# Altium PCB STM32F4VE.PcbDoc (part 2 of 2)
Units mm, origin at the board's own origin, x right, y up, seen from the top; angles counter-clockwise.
Board outline 98.7 x 95.5 mm, 2 copper layers (Top Layer, Bottom Layer); 103 components, 124 nets, 470 pads, 212 vias.
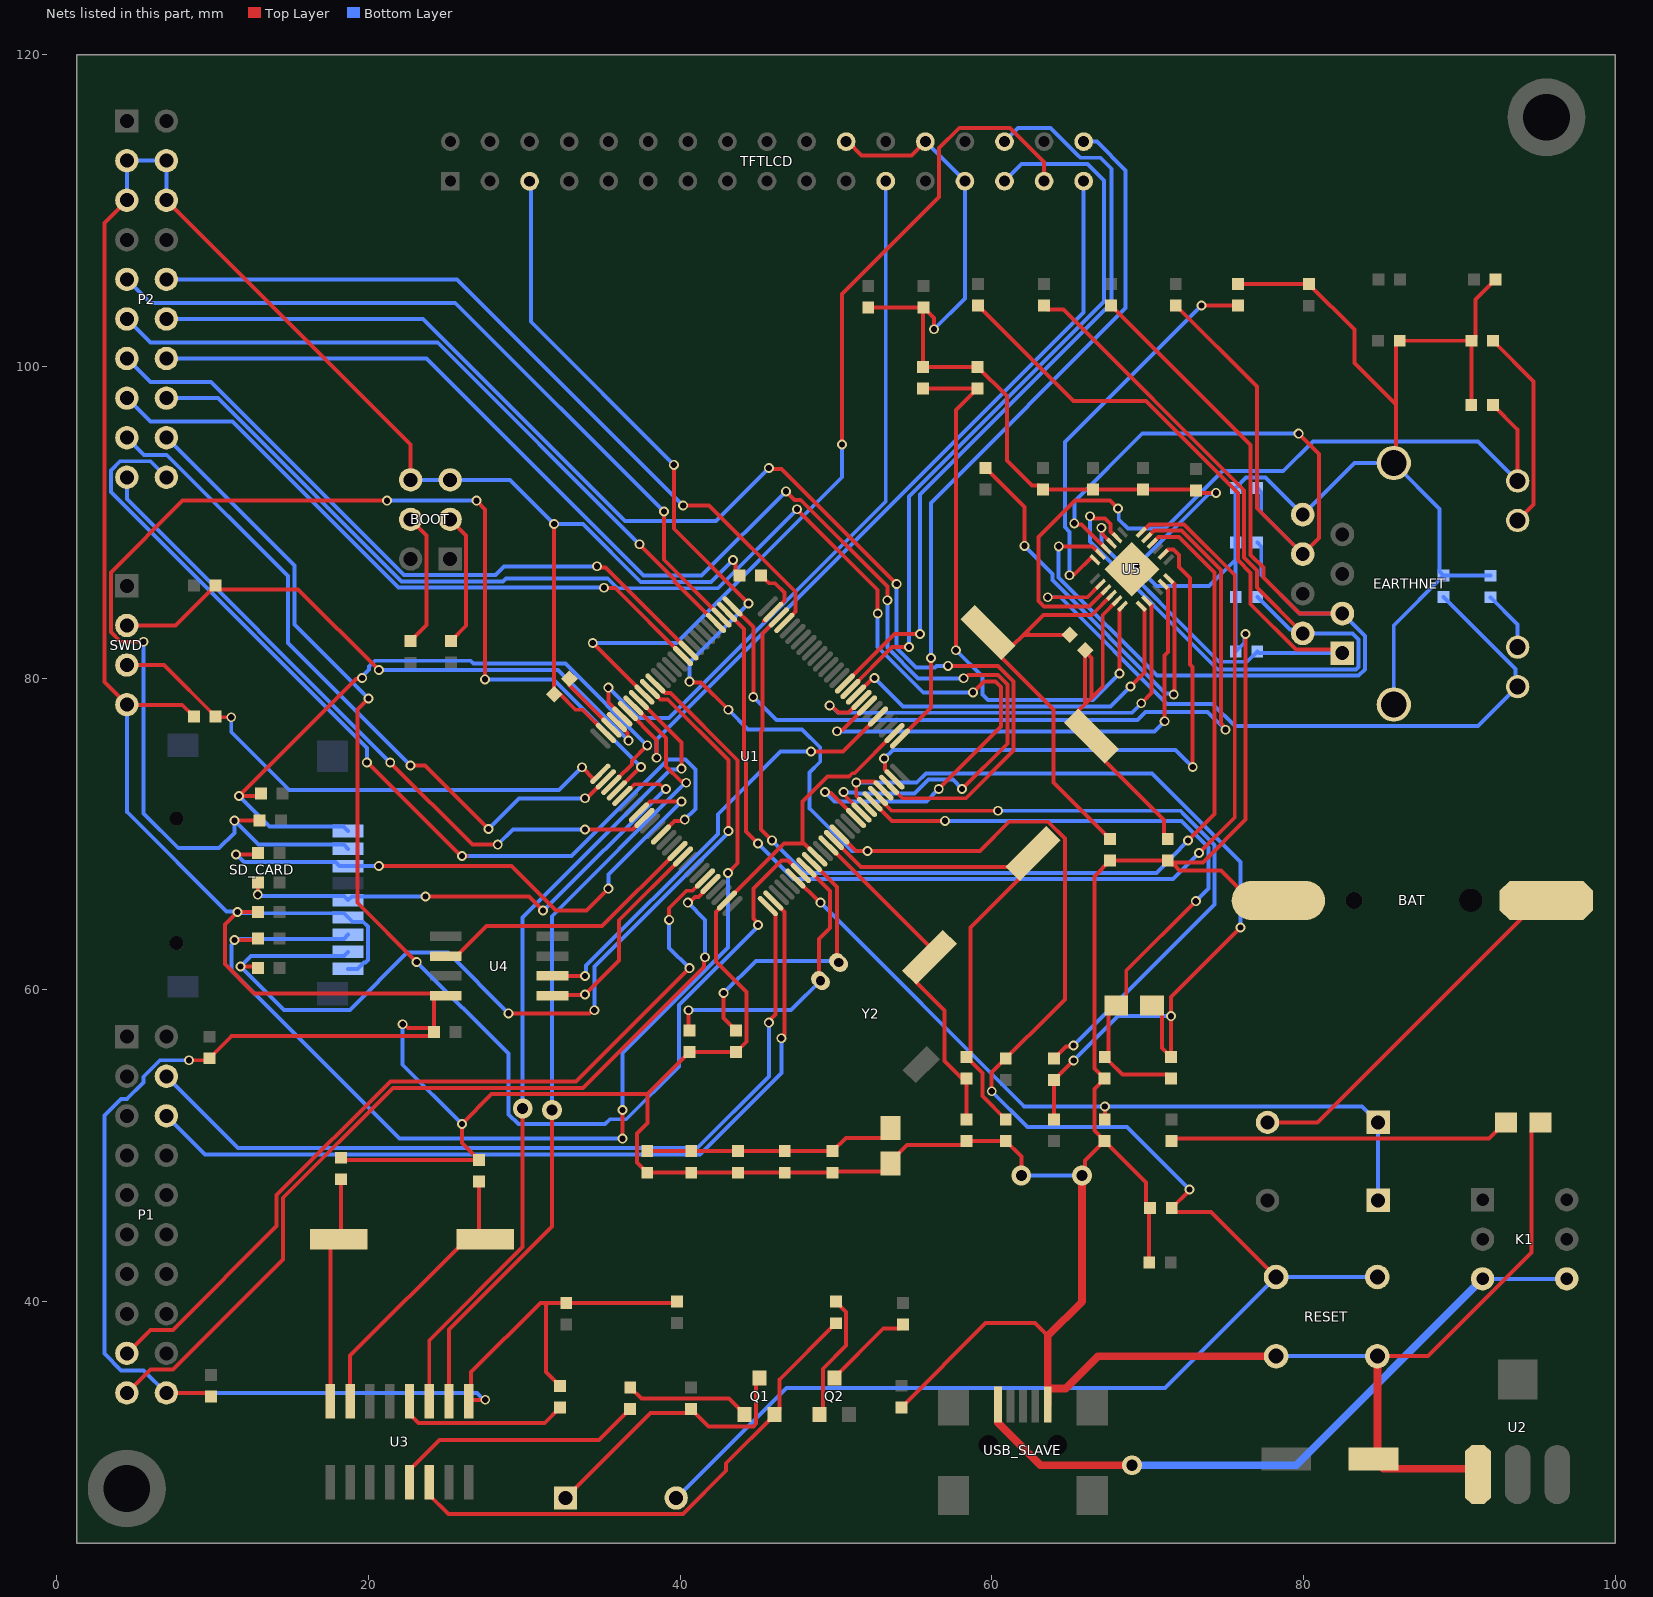
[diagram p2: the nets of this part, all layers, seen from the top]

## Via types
v1: diameter 0.635, hole 0.4, Top Layer to Bottom Layer, 197 vias
v2: diameter 1.27, hole 0.711, Top Layer to Bottom Layer, 15 vias

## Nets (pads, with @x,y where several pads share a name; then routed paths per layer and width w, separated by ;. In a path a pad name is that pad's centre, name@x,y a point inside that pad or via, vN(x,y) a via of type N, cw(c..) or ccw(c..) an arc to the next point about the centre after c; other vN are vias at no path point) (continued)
GND: BAT.2 BOOT.5 BOOT.6 C3.1 C4.1 C5.1 C6.1 C7.1 C8.1 C9.2 C10.2 C11.1 C12.1 C13.1 C14.1 C15.1 C16.1 C19.2 C20.2 C21.1 C22.1 C23.2 C24.1 C25.1 C26.1 C27.2 C28.1 C29.1 C30.1 C31.1 C32.1 C33.1 C34.2 C35.2 C36.1 C37.1 C38.1 C39.1 C40.1 C41.1 C42.1 C43.1 C44.1 C45.2 C46.2 DS1.2 EARTHNET.8 EARTHNET.13 EARTHNET.14 P1.20 P2.3 P2.4 P2.5 P2.6 R2.1 R18.1 R32.1 R33.1 R38.2 R39.2 R41.1 R42.1 RESET.2 SD_CARD.6 SD_CARD.9 SWD.4 TFTLCD.22 TFTLCD.26 TFTLCD.27 U1.10 U1.27 U1.74 U1.99 U2.1 U3.1 U4.4 U5.25 USB_SLAVE.5 | length 652.8
  Top Layer w0.254: P2.5@4.5,110.68 4.5,110.667 3.064,109.231 3.064,79.759 4.5,78.323 SWD.4@4.5,78.31 4.509,78.301 8.054,78.301 R18.1@8.814,77.541 ; P1.20@7.04,34.14 9.674,34.14 C43.1@9.9,33.914 ; P2.6@7.04,110.68 7.04,110.667 22.698,95.009 22.698,92.745 BOOT.6@22.707,92.736 ; v1(8.489,55.489) 9.672,55.489 11.23,57.048 23.948,57.048 C27.2@24.202,57.302 ; C28.1@12.914,65 v1(11.6,65) 10.803,64.203 10.803,61.653 12.673,59.782 24.093,59.782 24.312,59.563 24.202,59.452 C27.2@24.202,57.302 ; C26.1@18.398,49.087 C25.1@26.898,49.087 ; v1(22.2,57.8) 22.303,57.8 22.548,57.556 23.948,57.556 C27.2@24.202,57.302 ; U4.4@24.379,59.63 U4.4@24.956,59.63 ; U3.1@26.445,33.6 26.545,33.7 v1(27.5,33.7) ; U3.1@26.445,33.7 26.597,33.852 26.597,35.475 31.041,39.918 31.549,39.918 ; C25.1@27.1,49.086 26,50.186 v1(26,51.4) 27.914,53.314 37.9,53.314 ; v1(31.924,89.9) C11.1@31.924,78.981 32.283,78.981 33.282,77.982 33.74,77.982 U1.74@35.237,76.485 ; C24.1@32.046,34.84 31.4,35.486 31.4,39.77 31.549,39.918 ; C22.1@39.713,39.918 31.549,39.918 ; C14.1@40.6,56.014 37.9,53.314 ; C14.1@40.6,56.014 C13.1@43.6,56.014 44.262,56.676 44.262,59.858 42.3,61.82 42.3,65.002 43.015,65.716 U1.99@43.015,65.737 46.678,69.4 47.958,69.4 ; v1(43.4,87.6) 43.4,87.497 43.56,87.337 43.56,86.854 C12.1@43.814,86.6 ; U1.10@48.813,68.565 48.793,68.565 47.958,69.4 ; TFTLCD.22@50.662,114.441 50.773,114.441 51.653,113.562 54.85,113.562 55.729,114.441 TFTLCD.26@55.742,114.441 ; C46.2@52.079,103.802 C45.2@55.615,103.802 ; C3.1@53.438,48.922 54.564,50.047 58.128,50.047 C10.2@58.382,50.301 C9.2@60.9,50.301 61.9,49.302 v2(61.9,48.1) ; C3.1@53.502,48.858 52.994,48.35 49.87,48.35 C4.1@49.792,48.272 C8.1@37.893,48.272 37.234,48.931 37.234,50.79 37.9,51.456 37.9,53.314 ; U1.27@53.763,76.485 51.184,73.906 51.052,73.906 50.844,73.698 49.454,73.698 47.857,72.101 47.857,69.501 47.958,69.4 ; C21.1@54.2,33.214 59.6,38.614 62.786,38.614 63.6,37.8 ; v1(56.3,102.4) 56.3,103.117 55.632,103.785 55.598,103.752 C30.1@55.598,99.986 C29.1@59.097,99.986 60.969,98.113 60.969,93.987 62.588,92.368 63.046,92.368 C31.1@63.3,92.114 73.036,92.114 73.25,91.9 v1(74.4,91.9) ; USB_SLAVE.5@63.6,34.3 USB_SLAVE.5@63.723,34.423 ; v2(65.8,48.1) 65.994,48.294 65.994,49.058 C15.1@67.251,50.314 ; C19.2@70.109,42.502 70.109,45.939 C16.1@70.169,46 69.915,46.254 69.915,47.649 C15.1@67.251,50.314 ; C35.2@71.298,68.302 C34.2@67.598,68.302 66.592,67.295 66.592,54.973 R2.1@67.251,54.314 66.592,53.655 66.592,50.973 C15.1@67.251,50.314 ; C35.2@71.552,68.186 73.552,68.186 76.292,70.927 v1(76.292,82.848) ; C35.2@71.597,68.048 71.691,68.048 72.06,67.678 74.71,67.678 76.652,65.737 BAT.2@78.402,65.737 ; R32.1@75.811,105.307 80.337,105.307 83.268,102.375 83.268,100.224 85.932,97.561 ; C20.2@84.5,29.9 C20.2@84.751,30.151 ; RESET.2@84.751,36.5 87.996,36.5 94.638,43.142 94.638,50.99 95.146,51.498 DS1.2@95.211,51.498 ; EARTHNET.14@85.802,93.816 85.932,93.945 85.932,97.561 ; C42.1@86.186,101.663 R41.1@90.79,101.663 ; C42.1@86.186,101.663 85.932,101.409 85.932,97.561 ; R38.2@90.778,97.542 90.778,101.65 R41.1@90.79,101.663 ; U2.1@90.837,29.277 U2.1@91.21,28.904 ; C41.1@92.335,105.591 91.044,104.301 91.044,101.917 R41.1@90.79,101.663
  Top Layer w0.5: USB_SLAVE.5@63.6,33.4 63.6,34.3 63.6,37.8 65.8,40 v2(65.8,48.1) ; USB_SLAVE.5@63.723,34.423 64.754,34.423 66.826,36.495 78.246,36.495 RESET.2@78.251,36.5 ; C20.2@84.751,30.151 RESET.2@84.751,36.5 ; C20.2@85.123,29.277 U2.1@90.837,29.277
  Bottom Layer w0.254: SWD.4@4.5,78.31 4.509,78.301 4.509,71.434 10.901,65.042 11.558,65.042 v1(11.6,65) 11.703,65 11.78,64.923 18.427,64.923 18.973,64.377 19.668,64.377 19.979,64.066 19.979,61.934 19.816,61.771 19.721,61.771 19.3,61.35 SD_CARD.9@18.7,61.35 ; P2.5@4.5,110.68 P2.3@4.5,113.22 P2.4@7.04,113.22 P2.6@7.04,110.68 ; v1(8.489,55.489) 6.614,55.489 5.554,54.43 5.554,54.059 4.495,52.999 4.123,52.999 3.064,51.94 3.064,36.66 4.136,35.588 5.579,35.588 7.027,34.14 P1.20@7.04,34.14 7.049,34.131 26.966,34.131 27.397,33.7 v1(27.5,33.7) ; v1(22.2,57.8) 22.2,55.2 v1(26,51.4) ; BOOT.6@22.707,92.736 BOOT.5@25.247,92.736 25.256,92.726 29.098,92.726 v1(31.924,89.9) 33.761,89.9 37.477,86.184 41.984,86.184 v1(43.4,87.6) ; TFTLCD.26@55.742,114.441 TFTLCD.27@58.282,111.901 58.273,111.892 58.273,104.373 v1(56.3,102.4) ; v2(61.9,48.1) v2(65.8,48.1) ; v1(74.4,91.9) 74.327,91.827 73.927,91.827 v1(69.3,87.2) 70.589,85.91 73.946,85.91 75.66,87.625 ; v1(76.292,82.848) 76.219,82.776 76.219,82.281 C39.1@75.66,81.722 75.66,87.625 ; RESET.2@78.251,36.5 RESET.2@84.751,36.5 ; EARTHNET.13@85.802,78.316 85.802,83.4 R39.2@88.998,86.597 88.744,86.851 88.744,90.873 EARTHNET.14@85.802,93.816 83.279,93.816 79.969,90.506 79.951,90.506 77.573,92.884 76.322,92.884 C36.1@75.66,92.222 75.66,87.625 ; R39.2@89.011,86.584 R42.1@92,86.584
I2C_SCL: P1.17 U1.95 | length 55
  Top Layer w0.254: P1.17@4.5,36.68 6.011,38.191 7.466,38.191 14.114,44.838 14.114,46.835 21.407,54.127 33.329,54.127 v1(40.6,61.398) ; v1(39.3,64.5) 39.3,65.244 40.422,66.366 40.795,66.366 41.58,67.151 U1.95@41.601,67.151
  Bottom Layer w0.254: v1(39.3,64.5) 39.3,62.698 v1(40.6,61.398)
I2C_SDA: P1.19 U1.96 | length 57
  Top Layer w0.254: P1.19@4.5,34.14 6.011,35.651 7.466,35.651 14.521,42.705 14.521,46.667 21.575,53.721 33.767,53.721 41.528,61.482 41.528,62.027 v1(41.601,62.1) ; v1(40.5,65.6) 40.603,65.6 40.963,65.96 41.195,65.96 U1.96@41.84,66.604
  Bottom Layer w0.254: v1(40.5,65.6) 41.601,64.499 v1(41.601,62.1)
LCD_BL: TFTLCD.23 U1.71 | length 47.1
  Top Layer w0.254: v1(35.4,79.4) 35.4,78.464 36.298,77.566 U1.71@36.298,77.546
  Bottom Layer w0.254: v1(35.4,79.4) 37.343,77.457 39.301,77.457 53.202,91.357 TFTLCD.23@53.202,111.901
LINK_LED: EARTHNET.12 R38.1 U5.3 | length 50.8
  Top Layer w0.254: U5.3@67.337,85.691 66.249,84.603 63.353,84.603 63.003,84.953 63.003,89.066 65.34,91.403 67.597,91.403 v1(68.1,90.9) ; R38.1@92.162,97.54 93.75,95.952 EARTHNET.12@93.75,92.666
  Bottom Layer w0.254: v1(68.1,90.9) 68.154,90.846 68.154,90.201 68.753,89.603 71.128,89.603 74.816,93.29 78.709,93.29 80.614,95.195 91.221,95.195 EARTHNET.12@93.75,92.666
NetBAT_1: BAT.1 D2.1 | length 23.8
  Top Layer w0.254: D2.1@77.701,51.5 80.9,51.5 94.639,65.239 95.104,65.239 BAT.1@95.602,65.737
NetBOOT_3: BOOT.3 R5.2 | length 8.6
  Top Layer w0.254: BOOT.3@25.247,90.196 26.276,89.166 26.276,83.373 R5.2@25.302,82.399
NetBOOT_4: BOOT.4 R6.1 | length 8.7
  Top Layer w0.254: R6.1@22.707,82.386 23.736,83.415 23.736,89.166 BOOT.4@22.707,90.196
NetC1_1: C1.1 C2.1 R2.2 U1.20 | length 44
  Top Layer w0.254: U1.20@52.349,72.101 53.596,70.854 v1(57,70.854) ; R2.2@67.252,55.698 R2.2@67.372,55.818 ; C1.1@71.5,54.314 71.246,54.568 68.382,54.568 67.492,55.459 67.492,55.818 R2.2@67.372,55.818 ; v1(73.1,65.7) 68.635,61.235 68.635,59.506 68.127,58.998 C2.1@68,58.998 67.492,58.49 67.492,55.938 R2.2@67.372,55.818
  Bottom Layer w0.254: v1(57,70.854) 72.179,70.854 73.901,69.132 73.901,66.501 v1(73.1,65.7)
NetC9_1: C9.1 R4.2 U1.13 Y1.2 | length 31.3
  Top Layer w0.254: U1.13@49.874,69.626 51.608,67.892 61.792,67.892 61.792,67.156 58.637,64.001 58.637,55.952 R4.2@58.383,55.698 59.403,54.679 59.403,53.184 C9.1@60.902,51.686
NetC10_1: C10.1 R4.1 U1.12 Y1.1 | length 21.8
  Top Layer w0.254: U1.12@49.52,69.272 56,62.793 Y1.1@56,62.1 55.147,61.247 55.147,60.51 56.964,58.694 56.964,55.451 R4.1@58.1,54.314 ; C10.1@58.383,51.686 R4.1@58.382,54.314
NetC11_2: C11.2 U1.73 | length 4.2
  Top Layer w0.254: C11.2@32.904,79.958 32.904,79.525 U1.73@35.59,76.838
NetC12_2: C12.2 U1.49 | length 4.3
  Top Layer w0.254: C12.2@45.198,86.598 45.697,86.1 46.1,86.1 46.7,85.5 46.7,84.999 45.985,84.284 U1.49@45.985,84.263 45.964,84.263 U1.49@45.389,83.688
NetC13_2: C13.2 U1.9 Y2.1 | length 18.2
  Top Layer w0.254: v1(42.8,59.8) 42.8,58.2 C13.2@43.6,57.4 ; U1.9@48.46,68.212 50.068,66.603 50.068,61.866 Y2.1@50.174,61.76
  Bottom Layer w0.254: v1(42.8,59.8) 44.866,61.866 50.068,61.866 Y2.1@50.174,61.76
NetC14_2: C14.2 U1.8 Y2.2 | length 18.9
  Top Layer w0.254: v1(40.538,58.7) 40.538,57.462 C14.2@40.602,57.399 ; U1.8@48.106,67.858 49.611,66.353 49.611,63.972 48.908,63.269 48.908,60.706 Y2.2@49.014,60.6
  Bottom Layer w0.254: v1(40.538,58.7) 47.115,58.7 Y2.2@49.093,60.679
NetC24_2: C24.2 U3.4 | length 11.1
  Top Layer w0.254: U3.4@22.635,33.6 22.635,32.8 23.214,32.221 31.317,32.221 C24.2@32.298,33.201
NetC25_2: C25.2 U3.7 Y3.1 | length 18.6
  Top Layer w0.254: U3.7@18.825,33.6 18.825,36.531 26.294,44 Y3.1@27.5,44 27.098,44.402 C25.2@27.098,47.702
NetC26_2: C26.2 U3.8 Y3.2 | length 14.4
  Top Layer w0.254: U3.8@17.555,33.6 17.555,43.479 18.076,44 Y3.2@18.102,44 18.244,44.142 C26.2@18.244,47.703
NetC29_2: C29.2 C30.2 U5.6 | length 38.2
  Top Layer w0.254: C30.2@55.597,98.602 C29.2@59.095,98.602 57.7,97.206 57.7,81.806 v1@57.706,81.8 ; v1(68.2,80.3) 68.206,80.306 U5.6@68.206,84.436
  Bottom Layer w0.254: v1(57.7,81.8) 59.397,80.103 59.397,78.959 59.753,78.603 66.503,78.603 v1(68.2,80.3)
NetC34_1: C34.1 R40.1 U5.4 Y4.1 | length 28.1
  Top Layer w0.254: Y4.1@59.755,82.945 Y4.1@60.544,82.156 ; 62.281,82.945 62.441,82.785 ; R40.1@65.015,82.785 62.441,82.785 ; C34.1@67.6,69.686 63.977,73.309 63.977,77.987 60.608,81.356 60.608,82.092 61.344,82.092 62.037,82.785 ; U5.4@67.691,85.337 66.42,84.067 63.318,84.067 62.037,82.785 ; 62.037,82.785 62.441,82.785
NetC35_1: C35.1 R40.2 U5.5 Y4.2 | length 25.4
  Top Layer w0.254: Y4.2@66.4,76.3 65.547,77.153 65.547,77.89 65.993,78.335 ; Y4.2@66.443,76.343 66.443,75.52 71.046,70.918 71.046,69.94 C35.1@71.3,69.686 ; U5.5@68.045,84.984 67.126,84.066 67.126,79.469 66.4,78.743 ; 65.993,78.335 R40.2@65.993,81.805 65.993,81.714 66.4,81.307 66.4,78.743 ; 65.993,78.335 66.4,78.743
NetD3_2: D3.2 Q1.3 R23.1 | length 18.2
  Top Layer w0.254: D3.2@32.65,27.4 38.11,32.86 40.446,32.86 R23.1@40.7,33.114 41.817,31.998 44.716,31.998 44.879,32.161 44.879,34.881 Q1.3@45.1,35.102
NetDS1_1: DS1.1 R19.1 | length 21.9
  Top Layer w0.254: R19.1@71.545,50.313 71.703,50.471 91.908,50.471 92.936,51.498 DS1.1@93.001,51.498
NetEARTHNET_10: EARTHNET.10 R42.2 | length 3.9
  Bottom Layer w0.254: R42.2@92.002,85.2 93.75,83.451 EARTHNET.10@93.75,82.002
NetEARTHNET_11: EARTHNET.11 R41.2 | length 13
  Top Layer w0.254: R41.2@92.175,101.661 94.779,99.056 94.779,91.159 EARTHNET.11@93.75,90.13
NetQ1_1: Q1.1 R24.1 U3.14 | length 33.9
  Top Layer w0.254: U3.14@23.905,28.4 23.905,27.6 25.134,26.371 40.176,26.371 42.952,29.146 42.952,29.629 46.05,32.727 Q1.1@46.05,32.752 46.373,33.075 46.373,34.987 R24.1@50,38.614
NetQ1_2: Q1.2 R22.2 | length 8.1
  Top Layer w0.254: R22.2@36.802,34.498 37.526,33.775 43.152,33.775 44.15,32.777 Q1.2@44.15,32.752
NetQ2_2: Q2.2 R24.2 | length 8.2
  Top Layer w0.254: Q2.2@48.95,32.752 49.171,32.973 49.171,35.693 50.66,37.183 50.66,39.34 R24.2@50.002,39.999
NetQ2_3: Q2.3 R25.2 | length 5.8
  Top Layer w0.254: Q2.3@49.9,35.102 49.9,35.127 53.04,38.267 54.044,38.267 R25.2@54.298,38.521
NetR1_2: R1.2 U1.21 | length 40.7
  Top Layer w0.254: U1.21@52.973,72.106 53.578,71.5 v1(60.4,71.5) ; R1.2@64.002,55.599 64.769,56.366 65.18,56.366 v1(65.253,56.439)
  Bottom Layer w0.254: v1(60.4,71.5) 72.108,71.5 72.348,71.26 74.308,69.3 74.308,65.494 v1(65.253,56.439)
NetR22_1: R22.1 U3.13 | length 16.6
  Top Layer w0.254: U3.13@22.635,28.4 22.635,29.2 24.552,31.117 34.802,31.117 R22.1@36.8,33.114
NetR31_2: R31.2 U5.12 | length 27.4
  Top Layer w0.254: R31.2@59.602,93.499 62.1,91 v1(62.1,88.5) ; U5.12@71.37,86.398 71.37,86.395 71.72,86.045 71.72,79 v1(71.68,78.96)
  Bottom Layer w0.254: v1(62.1,88.5) 63.894,86.706 63.894,86.302 71.163,79.033 71.607,79.033 v1(71.68,78.96)
NetR32_2: R32.2 U5.24 | length 25.6
  Top Layer w0.254: v1(65,86.615) 65.073,86.688 65.33,86.688 66.436,87.793 66.439,87.793 U5.24@66.63,87.602 ; v1(73.457,103.923) R32.2@75.81,103.923
  Bottom Layer w0.254: v1(65,86.615) 65,89.4 64.703,89.697 64.703,95.169 v1(73.457,103.923)
PA0: P2.12 U1.23 | length 83.3
  Top Layer w0.254: v1(45.7,93.5) 45.756,93.444 46.502,93.444 v1(53.9,86.045) ; U1.23@53.41,73.161 53.43,73.161 54.289,72.303 58.349,72.303 61.41,75.364 61.41,79.784 60.393,80.8 v1(57.2,80.8)
  Bottom Layer w0.254: P2.12@7.04,103.06 23.515,103.06 36.472,90.103 42.303,90.103 v1(45.7,93.5) ; v1(53.9,86.045) 53.9,81.957 55.154,80.703 56.347,80.703 56.444,80.8 57.024,80.8 v1@57.103,80.721
PA15: P2.17 U1.77 | length 45
  Top Layer w0.254: v1(22.7,74.4) 23.633,74.4 v1(27.7,70.333) ; v1(33.9,72.3) 34.001,72.3 35.216,73.515 U1.77@35.237,73.515
  Bottom Layer w0.254: P2.17@4.5,95.44 5.604,94.336 7.06,94.336 14.844,86.552 14.844,82.256 v1(22.7,74.4) ; v1(27.7,70.333) 29.667,72.3 v1(33.9,72.3)
PB10: P2.10 U1.47 | length 51
  Top Layer w0.254: v1(40.2,91.097) 41.857,91.097 47.4,85.554 47.4,84.285 46.692,83.577 U1.47@46.692,83.556
  Bottom Layer w0.254: P2.10@7.04,105.6 25.697,105.6 v1(40.2,91.097)
PB14: P2.9 U1.53 | length 49
  Top Layer w0.254: v1(38.964,90.7) 38.964,87.607 U1.53@42.661,83.91
  Bottom Layer w0.254: P2.9@4.5,105.6 6.011,104.089 25.574,104.089 v1(38.964,90.7)
PB15: P2.11 U1.54 | length 46
  Top Layer w0.254: v1(37.4,88.6) 37.4,88.596 39.648,86.348 39.648,86.216 U1.54@42.308,83.556
  Bottom Layer w0.254: P2.11@4.5,103.06 6.011,101.549 24.451,101.549 v1(37.4,88.6)
PC2: P2.16 U1.17 | length 87.1
  Top Layer w0.254: v1(47.5,90.846) 52.686,85.66 v1(52.686,84.152) ; v1(49.3,72.7) 49.373,72.627 49.701,72.627 U1.17@51.288,71.04 ; v1(56.6,72.9) 60.597,76.897 60.597,79.447 60.247,79.797 59.497,79.797 v1(58.8,79.1)
  Bottom Layer w0.254: P2.16@7.04,97.98 10.352,97.98 22.112,86.22 28.641,86.22 28.832,86.41 35.361,86.41 35.993,85.778 42.432,85.778 v1(47.5,90.846) ; v1(49.3,72.7) 49.897,72.103 55.803,72.103 v1(56.6,72.9) ; v1(52.686,84.152) 52.686,82.022 55.608,79.1 v1(58.8,79.1)
PC3: P2.14 U1.18 | length 87.5
  Top Layer w0.254: v1(46.8,92) 47.358,91.442 47.747,91.442 53.303,85.887 v1(53.303,85.009) ; v1(50.5,72.7) 50.573,72.627 50.573,72.463 U1.18@51.642,71.394 ; v1(58.102,72.9) 61.003,75.802 61.003,79.615 60.415,80.203 58.506,80.203 58.303,80 v1(58.2,80)
  Bottom Layer w0.254: P2.14@7.04,100.52 23.716,100.52 37.646,86.591 41.391,86.591 v1(46.8,92) ; v1(50.5,72.7) 50.543,72.657 51.199,72.657 51.253,72.603 55.059,72.603 55.953,73.497 57.505,73.497 v1(58.102,72.9) ; v1(53.303,85.009) 53.303,81.98 55.283,80 v1(58.2,80)
PC13: P2.18 U1.7 | length 83.6
  Top Layer w0.254: v1(20,78.7) 19.303,78.003 19.303,65.597 v1(23.1,61.8) ; v1(45,64.172) 45,64.275 44.703,64.572 44.703,66.501 46.503,68.302 46.935,68.302 47.732,67.505 U1.7@47.753,67.505
  Bottom Layer w0.254: P2.18@7.04,95.44 15.25,87.23 15.25,83.45 v1(20,78.7) ; v1(23.1,61.8) 28.986,55.914 28.986,52.021 29.621,51.386 35.196,51.386 35.514,51.703 36.547,51.703 39.941,55.097 39.941,59.022 45,64.08 v1(45,64.172)
PD3: P2.19 U1.84 | length 44.4
  Top Layer w0.254: v1(21.4,74.6) 26.677,69.323 28.177,69.323 v1@28.2,69.3 ; v1(33.9,70.3) 36.951,70.3 37.691,71.04 U1.84@37.712,71.04
  Bottom Layer w0.254: P2.19@4.5,92.9 4.5,91.5 v1(21.4,74.6) ; v1(28.3,69.323) 29.277,70.3 v1(33.9,70.3)
PD6: P2.20 U1.87 | length 61.9
  Top Layer w0.254: v1(19.9,74.596) 19.952,74.596 25.948,68.6 v1@26.3,68.6 ; U1.87@38.772,69.98 39.647,70.854 40.227,70.854 v1(40.3,70.927)
  Bottom Layer w0.254: P2.20@7.04,92.9 6.011,93.929 4.074,93.929 3.471,93.326 3.471,91.955 19.9,75.525 v1(19.9,74.596) ; v1(26,68.6) 33.044,68.6 39.241,74.797 40.342,74.797 40.997,74.142 40.997,71.624 v1(40.3,70.927)
PD12: P2.13 U1.59 | length 44.3
  Top Layer w0.254: v1(34.672,87.188) 34.744,87.115 35.214,87.115 U1.59@40.54,81.788
  Bottom Layer w0.254: P2.13@4.5,100.52 6.011,99.009 9.897,99.009 22.281,86.626 28.144,86.626 28.705,87.188 v1(34.672,87.188)
PD13: P2.15 U1.60 | length 42.5
  Top Layer w0.254: v1(35.113,85.813) 35.117,85.809 35.812,85.809 U1.60@40.187,81.435
  Bottom Layer w0.254: P2.15@4.5,97.98 6.011,96.469 11.288,96.469 21.944,85.813 v1(35.113,85.813)
PWDN: P1.4 U1.1 | length 53.8
  Top Layer w0.254: U1.1@45.631,65.383 46.116,64.899 46.116,58.419 45.7,58.003 v1(45.7,57.9)
  Bottom Layer w0.254: P1.4@7.04,54.46 11.64,49.86 41.104,49.86 45.7,54.456 v1(45.7,57.9)
RESET: C16.2 D3.1 R16.2 RESET.1 TFTLCD.5 U1.14 | length 169.4
  Top Layer w0.254: v1(39.603,93.7) 39.603,89.597 v1(44.4,84.8) ; v1(40.6,79.784) 40.66,79.724 41.358,79.724 v1(43.1,77.982) ; U1.14@50.228,69.98 51.288,68.919 59.238,68.919 61.113,70.794 63.614,70.794 64.694,69.714 64.694,59.391 60,54.697 v1(60,53.5) ; v1(72.7,47.2) 72.7,47.145 C16.2@71.554,45.998 71.808,45.744 74.086,45.744 RESET.1@78.251,41.58
  Bottom Layer w0.254: TFTLCD.5@30.344,111.895 30.423,111.816 30.423,102.88 v1(39.603,93.7) ; D3.1@39.75,27.4 39.763,27.4 46.826,34.463 71.133,34.463 RESET.1@78.251,41.58 RESET.1@84.751,41.58 ; v1(40.6,79.784) 40.6,81 v1(44.4,84.8) ; v1(43.1,77.982) 44.354,76.728 47.816,76.728 48.997,75.547 48.997,74.645 48.297,73.945 48.297,71.659 51.037,68.919 v1(52.034,68.919) ; v1(60,53.5) 62.285,51.214 68.686,51.214 v1(72.7,47.2)
RMII_CRS_DV: U1.32 U5.11 | length 32.9
  Top Layer w0.254: v1(50.071,76.6) 50.144,76.673 50.416,76.673 U1.32@51.995,78.253 ; U5.11@71.016,86.045 71.016,86.042 71.313,85.745 71.313,81.696 71.083,81.466 71.083,77.258 v1(71.1,77.241)
  Bottom Layer w0.254: v1(50.071,76.6) 70.459,76.6 v1(71.1,77.241)
RMII_REF_CLK: U1.24 U5.14 | length 37.3
  Top Layer w0.254: v1(53.1,74.847) 53.15,74.797 53.15,74.148 53.763,73.536 U1.24@53.763,73.515 ; U5.14@71.016,87.955 71.019,87.955 71.316,88.252 71.68,88.252 72.02,87.912 72.02,87.14 72.735,86.425 72.735,80.883 72.9,80.718 v1(72.9,74.3)
  Bottom Layer w0.254: v1(53.1,74.847) 53.652,75.399 71.801,75.399 v1(72.9,74.3)
RMII_RXD0: U1.33 U5.8 | length 30
  Top Layer w0.254: v1(49.6,78.253) 49.703,78.253 50.156,77.8 50.815,77.8 51.621,78.606 U1.33@51.642,78.606 ; v1(69.6,78.4) 70.253,79.053 70.253,84.684 69.955,84.981 U5.8@69.955,84.984
  Bottom Layer w0.254: v1(49.6,78.253) 49.663,78.253 50.125,77.79 68.99,77.79 v1(69.6,78.4)
RMII_RXD1: U1.34 U5.7 | length 25
  Top Layer w0.254: U1.34@51.288,78.96 51.309,78.96 52.369,80.02 v1(52.471,80.02) ; v1(68.9,79.466) 69.794,80.359 69.794,84.439 U5.7@69.602,84.63
  Bottom Layer w0.254: v1@52.596,80.096 52.596,79.896 54.295,78.197 67.631,78.197 v1(68.9,79.466)
RMII_TX_EN: U1.48 U5.16 | length 66.5
  Top Layer w0.254: v1(45.9,69.6) 45.203,70.297 45.203,76.577 45.297,76.671 45.297,82.868 U1.48@46.338,83.91 ; U5.16@70.309,88.663 70.312,88.663 70.715,89.065 72.016,89.065 74.297,86.785 74.297,71.3 v1(72.593,69.596)
  Bottom Layer w0.254: v1@45.902,69.598 47.987,67.513 70.562,67.513 v1(72.593,69.596)
RMII_TXD0: U1.51 U5.17 | length 54.3
  Top Layer w0.254: U1.51@43.369,84.617 44.7,83.285 v1(44.7,78.8) ; U5.17@69.955,89.016 69.958,89.016 70.414,89.472 72.185,89.472 74.703,86.953 74.703,77.1 75,76.803 v1(75,76.7)
  Bottom Layer w0.254: v1(44.7,78.8) 46.19,77.31 69.354,77.31 69.882,77.838 73.862,77.838 v1(75,76.7)
RMII_TXD1: U1.52 U5.18 | length 72
  Top Layer w0.254: U1.52@43.015,84.263 44.103,83.175 44.103,74.908 44.221,74.791 44.221,70.18 v1(45,69.4) ; U5.18@69.602,89.37 69.605,89.37 70.113,89.878 72.353,89.878 75.597,86.634 75.597,71.076 v1(73.304,68.783)
  Bottom Layer w0.254: v1(45,69.4) 47.293,67.107 71.628,67.107 v1(73.304,68.783)
RST: P1.6 U1.2 | length 54.1
  Top Layer w0.254: U1.2@45.985,65.737 45.985,65.716 46.7,65.001 46.7,57.1 v1(46.5,56.9)
  Bottom Layer w0.254: P1.6@7.04,51.92 9.506,49.454 41.273,49.454 46.5,54.681 v1(46.5,56.9)
RXD: U1.68 U3.3 | length 53.2
  Top Layer w0.254: U3.3@23.905,33.6 23.905,37.508 29.9,43.503 v2(29.9,52.4) ; U1.68@37.358,78.606 40.095,75.869 v1(40.095,74.2)
  Bottom Layer w0.254: v2(29.9,52.4) 29.9,64.638 39.397,74.134 40.029,74.134 v1(40.095,74.2)
SDIO_CMD: R26.1 SD_CARD.3 U1.83 | length 38
  Top Layer w0.254: v1(11.5,68.7) 12.814,68.7 R26.1@12.914,68.8 ; v1(20.669,67.95) 29.187,67.95 32.034,65.103 34.003,65.103 v1(35.4,66.5) ; U1.83@37.358,71.394 37.379,71.394 38.085,72.1 v1(40.095,72.1)
  Bottom Layer w0.254: v1(11.5,68.7) 11.534,68.7 12.011,68.223 17.881,68.223 18.154,67.95 v1(20.669,67.95) ; v1(35.4,66.5) 35.4,67.405 v1(40.095,72.1)
SDIO_D0: R29.1 SD_CARD.7 U1.65 | length 75.3
  Top Layer w0.254: v1(11.4,63.2) 12.814,63.2 R29.1@12.914,63.3 ; v1(36.3,50.457) v1(36.3,52.3) ; U1.65@38.419,79.588 U1.65@38.419,79.667 38.439,79.667 39.049,79.057 39.379,79.057 43.697,74.74 43.697,68.132 v1(43.078,67.513)
  Bottom Layer w0.254: SD_CARD.7@18.7,63.55 18.427,63.277 11.58,63.277 11.503,63.2 v1(11.4,63.2) 11.4,63.097 11.203,62.9 11.203,61.253 21.999,50.457 v1(36.3,50.457) ; v1(36.3,52.3) 36.3,55.955 43.078,62.733 v1(43.078,67.513)
SDIO_D1: R30.1 SD_CARD.8 U1.66 | length 62.1
  Top Layer w0.254: v1(11.8,61.5) 12.814,61.5 R30.1@12.914,61.4 ; v1(29,58.5) 34.197,58.5 34.397,58.7 v1(34.5,58.7) ; U1.66@38.065,79.313 38.086,79.313 38.748,78.651 39.211,78.651 43.1,74.762 v1(43.1,70.2)
  Bottom Layer w0.254: SD_CARD.8@18.7,62.45 18.427,62.177 12.477,62.177 v1(11.8,61.5) 14.579,58.721 18.816,58.721 22.492,62.397 25.103,62.397 v1(29,58.5) ; v1(34.5,58.7) 34.5,61.516 43.1,70.116 v1(43.1,70.2)
SDIO_D2: R28.1 SD_CARD.1 U1.78 | length 44.5
  Top Layer w0.254: R28.1@13.114,72.6 13.014,72.5 12.969,72.454 v1(11.7,72.454) 19.193,79.948 19.527,79.948 v1(19.6,80.02) ; U1.78@36.029,73.6 36.903,74.474 36.903,74.71 v1(37.893,75.7)
  Bottom Layer w0.254: v1(11.7,72.454) 13.656,70.498 18.402,70.498 SD_CARD.1@18.7,70.2 ; v1(19.6,80.02) 19.6,80.113 20.047,80.561 20.047,80.753 20.422,81.128 26.544,81.128 26.734,80.937 32.656,80.937 v1(37.893,75.7)
SDIO_D3: R27.1 SD_CARD.2 U1.79 | length 86.4
  Top Layer w0.254: v1(5.563,82.347) 4.087,82.347 3.471,82.964 3.471,86.796 8.075,91.4 v1(21.2,91.4) ; v1(11.4,70.864) 13.013,70.864 R27.1@13.014,70.865 ; v1(26.931,91.4) 27.497,90.834 27.497,79.948 v1(27.483,79.934) ; U1.79@35.944,72.808 35.965,72.808 37.457,74.3 v1(37.5,74.3)
  Bottom Layer w0.254: v1(5.563,82.347) 5.563,71.337 7.8,69.1 10.421,69.1 11.4,70.079 v1(11.4,70.864) 12.941,69.323 18.427,69.323 SD_CARD.2@18.7,69.05 ; v1(21.2,91.4) v1(26.931,91.4) ; v1(27.483,79.934) 31.866,79.934 v1(37.5,74.3)
SDIO_SCK: R43.1 SD_CARD.5 U1.80 | length 34.1
  Top Layer w0.254: v1(12.903,66.116) 12.903,66.889 R43.1@12.914,66.9 ; v1(23.673,66) 30.293,66 v1(31.2,65.093) ; U1.80@36.298,72.454 36.318,72.454 37.064,73.2 38.697,73.2 38.997,72.9 v1(39.1,72.9)
  Bottom Layer w0.254: v1(12.903,66.116) 13.006,66.116 13.099,66.023 18.438,66.023 18.7,65.761 18.939,66 v1(23.673,66) ; v1(31.2,65.093) 31.247,65.093 39.053,72.9 v1(39.1,72.9)
SPEED_LED: EARTHNET.9 R39.1 U5.2 | length 46.1
  Top Layer w0.254: v1(63.6,85.2) 66.139,85.2 U5.2@66.984,86.045
  Bottom Layer w0.254: v1(63.6,85.2) 64.421,85.2 71.258,78.363 74.181,78.363 75.608,76.936 91.221,76.936 EARTHNET.9@93.75,79.466 93.616,79.6 93.616,80.597 R39.1@89,85.212
SPI1_MISO: U1.90 U4.2 | length 17.7
  Top Layer w0.254: U4.2@24.956,62.17 25.667,62.17 27.587,64.09 35.004,64.09 U1.90@39.833,68.919
SPI1_MOSI: U1.91 U4.5 | length 13.6
  Top Layer w0.254: U4.5@31.814,59.632 31.848,59.666 33.864,59.666 36.094,61.895 36.094,64.472 U1.91@40.187,68.565
  other v1: 33.898,59.7
SPI1_SCK: U1.30 U4.6 | length 28.9
  Top Layer w0.254: U4.6@31.814,60.902 v1(33.898,60.902) ; v1(48.4,75.3) 50.457,75.3 U1.30@52.702,77.546
  Bottom Layer w0.254: v1(33.898,60.902) 33.971,60.975 33.971,61.562 42.431,70.022 42.431,71.275 46.456,75.3 v1(48.4,75.3)
SWCLK: R18.2 SWD.3 U1.76 | length 35.3
  Top Layer w0.254: SWD.3@4.5,80.85 6.888,80.85 10.237,77.5 v1(11.2,77.5) ; v1(33.709,74.295) 34.484,73.519 34.534,73.519 U1.76@34.883,73.869
  Bottom Layer w0.254: v1(11.2,77.5) 11.2,76.552 14.921,72.831 32.244,72.831 v1(33.709,74.295)
SWDIO: R17.2 SWD.2 U1.72 | length 38.9
  Top Layer w0.254: SWD.2@4.5,83.39 7.626,83.39 R17.2@10.199,85.962 10.453,85.708 15.492,85.708 v1(20.669,80.531) ; U1.72@35.944,77.192 35.944,77.171 36.627,76.488 36.627,76.073 v1(36.7,76)
  Bottom Layer w0.254: v1(20.669,80.531) 32.169,80.531 v1(36.7,76)
T_CS: TFTLCD.33 U1.70 | length 52.1
  Top Layer w0.254: U1.70@36.651,77.899 38.5,76.05 v1(38.5,74.9)
  Bottom Layer w0.254: v1(38.5,74.9) 38.5,76.081 65.902,103.483 TFTLCD.33@65.902,111.901
T_MISO: TFTLCD.29 U1.35 | length 47.3
  Top Layer w0.254: U1.35@50.935,79.313 50.935,79.328 53.608,82.002 v1(54.7,82.002)
  Bottom Layer w0.254: v1(54.7,82.002) 54.7,91.673 67.2,104.173 67.2,111.938 66.138,113 61.921,113 TFTLCD.29@60.822,111.901
T_MOSI: TFTLCD.30 U1.36 | length 49.4
  Top Layer w0.254: U1.36@50.581,79.667 53.762,82.848 v1(55.4,82.848)
  Bottom Layer w0.254: v1(55.4,82.848) 55.4,91.798 67.7,104.098 67.7,112.7 66.994,113.406 65.692,113.406 65.506,113.593 63.778,115.32 61.701,115.32 TFTLCD.30@60.822,114.441
T_PEN: TFTLCD.31 U1.67 | length 58.2
  Top Layer w0.254: v1(34.4,82.268) 34.402,82.268 37.71,78.96 U1.67@37.712,78.96 ; v1(50.4,95) 50.4,104.662 56.621,110.883 56.621,114.024 57.917,115.32 61.186,115.32 63.362,113.145 TFTLCD.31@63.362,111.901
  Bottom Layer w0.254: v1(34.4,82.268) 39.766,82.268 50.4,92.901 v1(50.4,95)
T_SCK: TFTLCD.34 U1.26 | length 45.9
  Top Layer w0.254: U1.26@54.117,76.131 56.1,78.115 v1(56.1,81.3)
  Bottom Layer w0.254: v1(56.1,81.3) 56.1,91.256 68.6,103.756 68.6,112.6 66.759,114.441 TFTLCD.34@65.902,114.441
TPRX+: C37.2 EARTHNET.3 R36.1 U5.23 | length 67.7
  Top Layer w0.254: v1(64.3,88.47) 66.467,88.47 66.981,87.955 U5.23@66.984,87.955 ; R36.1@67.65,103.923 76.606,94.966 76.606,87.924 77.432,87.098 77.432,86.481 79.757,84.156 EARTHNET.3@82.5,84.156
  Bottom Layer w0.254: v1@64.5,88.5 64.33,88.5 v1(64.3,88.47) 64.3,86.47 70.603,80.168 83.546,80.168 83.948,80.57 83.948,82.708 EARTHNET.3@82.5,84.156 79.757,84.156 77.298,86.615 77.298,88.47 C37.2@77.044,88.724
TPRX-: C36.2 EARTHNET.6 R37.1 U5.22 | length 53.8
  Top Layer w0.254: v1(65.3,89.944) 65.373,89.871 65.775,89.871 U5.22@67.337,88.309 ; R37.1@71.809,103.923 77.013,98.719 77.013,90.913 EARTHNET.6@79.96,87.966 81.001,89.007 81.001,94.399 v1(79.7,95.7)
  Bottom Layer w0.254: v1(65.3,89.944) 65.3,91.338 69.662,95.7 v1(79.7,95.7) ; C36.2@77.044,92.224 77.298,91.97 77.298,90.627 EARTHNET.6@79.96,87.966
TPTX+: C39.2 EARTHNET.1 R34.1 U5.21 | length 57.5
  Top Layer w0.254: R34.1@59.123,103.921 65.261,97.783 69.91,97.783 75.794,91.899 75.794,87.587 76.619,86.762 76.619,84.754 79.529,81.844 82.271,81.844 EARTHNET.1@82.5,81.616 ; v1(67.036,89.664) 67.109,89.591 67.109,89.244 U5.21@67.691,88.663
  Bottom Layer w0.254: v1(67.036,89.664) 67.036,88.619 74.594,81.062 76.382,81.062 C39.2@77.044,81.724 77.152,81.616 EARTHNET.1@82.5,81.616
TPTX-: C38.2 EARTHNET.2 R35.1 U5.20 | length 62.8
  Top Layer w0.254: R35.1@63.365,103.921 63.619,103.667 64.6,103.667 76.2,92.068 76.2,87.755 77.026,86.93 77.026,85.82 EARTHNET.2@79.96,82.886 ; v1(66.3,90.4) 66.403,90.4 66.542,90.26 67.284,90.26 67.633,89.911 67.633,89.43 68.045,89.019 U5.20@68.045,89.016
  Bottom Layer w0.254: v1(66.3,90.4) 66.3,88.781 74.507,80.574 83.378,80.574 83.541,80.738 83.541,82.493 83.149,82.886 EARTHNET.2@79.96,82.886 79.717,83.129 79.139,83.129 C38.2@77.044,85.224
TXD: U1.69 U3.2 | length 52.5
  Top Layer w0.254: U3.2@25.175,33.6 25.175,38.203 31.785,44.813 v2(31.785,52.3) ; U1.69@37.005,78.253 39.097,76.16 39.097,74.354 40.078,73.373 40.327,73.373 v1(40.4,73.3)
  Bottom Layer w0.254: v2(31.785,52.3) 31.785,64.729 40.356,73.3 v1(40.4,73.3)
VBAT: C15.2 D1.2 D2.2 U1.6 | length 49.7
  Top Layer w0.254: U1.6@47.399,67.151 47.42,67.151 48.971,65.6 v1(49.014,65.6) ; C15.2@67.252,51.698 67.259,51.705 v1(67.259,52.527)
  Bottom Layer w0.254: v1(49.014,65.6) 62.087,52.527 v1(67.259,52.527) 67.261,52.529 83.771,52.529 D2.2@84.801,51.5 D1.2@84.801,46.498
VCC: C3.2 C4.2 C5.2 C6.2 C7.2 C8.2 | length 16.3
  Top Layer w0.254: C8.2@37.894,49.656 C4.2@49.794,49.656 50.646,50.509 52.994,50.509 53.502,51.017 C3.2@53.502,51.144
VDDA: C1.2 C2.2 R1.1 R3.2 U1.19 U1.22 | length 61.1
  Top Layer w0.254: U1.19@51.995,71.747 51.995,71.768 51.309,72.454 v1(51.309,73.309) 51.383,73.383 52.46,73.383 53.035,72.808 U1.22@53.056,72.808 ; R3.2@64.002,51.698 R1.1@64,54.214 R1.1@64,54.214 v1(65.259,55.474) ; C2.2@70.286,58.998 70.413,58.998 70.921,58.49 70.921,56.279 C1.2@71.502,55.699 v1(71.502,58.318) 71.502,59.538 v1(75.971,64.008)
  Bottom Layer w0.254: v1(51.309,73.309) 55.19,73.309 55.784,73.903 70.28,73.903 75.971,68.211 v1(75.971,64.008) ; v1(65.259,55.474) 68.104,58.318 v1(71.502,58.318)
VUSB: K1.3 K1.4 USB_SLAVE.1 | length 43.8
  Top Layer w0.254: USB_SLAVE.1@60.4,32.5 USB_SLAVE.1@60.4,33.4
  Top Layer w0.5: USB_SLAVE.1@60.4,32.5 60.4,32.231 63.131,29.5 v2(69,29.5)
  Bottom Layer w0.254: K1.3@91.5,41.46 K1.4@96.9,41.46
  Bottom Layer w0.5: v2(69,29.5) 79.54,29.5 K1.3@91.5,41.46
pads on no net: BAT.0 EARTHNET.7 K1.1 K1.6 P1.8 P1.14 P1.16 SD_CARD.0 SD_CARD.10 TFTLCD.32 U3.9 U3.10 U3.11 U3.12 U3.15 U5.10 USB_SLAVE.4 USB_SLAVE.6 USB_SLAVE.7 USB_SLAVE.8 USB_SLAVE.9 USB_SLAVE.MH1 USB_SLAVE.MH2 Y2.3

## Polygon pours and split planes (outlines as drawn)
no net on Top Layer (solid, pour order 0): 1.3,120 100,120 100,24.5 1.3,24.5
no net on Bottom Layer (solid, pour order 2): 1.3,120 100,120 100,24.5 1.3,24.5

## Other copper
Top Layer:
  region net T_MOSI: 53.584,81.6
  region: 80.349,103.909
  region: 80.6,104

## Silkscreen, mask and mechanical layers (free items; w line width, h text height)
Top Overlay:
  lines w0.254: 9,94.2 18.525,94.2 ; 9,96.8 18.525,96.8 ; 9,99.3 18.525,99.3 ; 9,101.8 18.525,101.8 ; 9,104.3 18.525,104.3 ; 9,106.9 18.425,106.9 ; 9,109.5 18.525,109.5 ; 9,112 18.425,112 ; 9,114.5 18.525,114.5 ; 13.6,91.7 13.6,117.5 ; 9,91.8 9.2,91.6 18.45,91.6 18.525,91.675 18.525,92.975 18.525,116.125 18.525,117.5 9.5,117.5 9,117 9,91.8
  text "5V" at 10.5,115.4 h1
  text "5V" at 15.5,115.4 h1
  text "GND" at 10,112.6 h1
  text "GND" at 14.8,112.6 h1
  text "GND" at 10,110.2 h1
  text "GND" at 14.8,110.2 h1
  text "3V3" at 10,107.7 h1
  text "3V3" at 14.8,107.7 h1
  text "PB14" at 9.7,105 h1
  text "PB10" at 14.5,105 h1
  text "PB15" at 9.7,102.5 h1
  text "PA0" at 14.8,102.5 h1
  text "PD12" at 9.7,100 h1
  text "PC3" at 14.8,100 h1
  text "PD13" at 9.7,97.5 h1
  text "PC2" at 14.8,97.5 h1
  text "PA15" at 9.7,95 h1
  text "PC13" at 14.5,95 h1
  text "PD3" at 10,92.5 h1
  text "PD6" at 14.8,92.5 h1
Mechanical 1:
  lines w0.254: 1.173,24.5 ccw(c1.3,24.5) 1.3,24.373 ; 1.173,24.5 ccw(c1.3,24.5) 1.3,24.373 ; 1.173,24.5 1.173,120 ; 1.173,120 cw(c1.3,120) 1.3,120.127 ; 1.173,120 cw(c1.3,120) 1.3,120.127 ; 1.3,24.373 100,24.373 ; 1.3,120.127 100,120.127 ; 100,24.373 ccw(c100,24.5) 100.127,24.5 ; 100,24.373 ccw(c100,24.5) 100.127,24.5 ; 100,120.127 cw(c100,120) 100.127,120 ; 100,120.127 cw(c100,120) 100.127,120 ; 100.127,24.5 100.127,120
